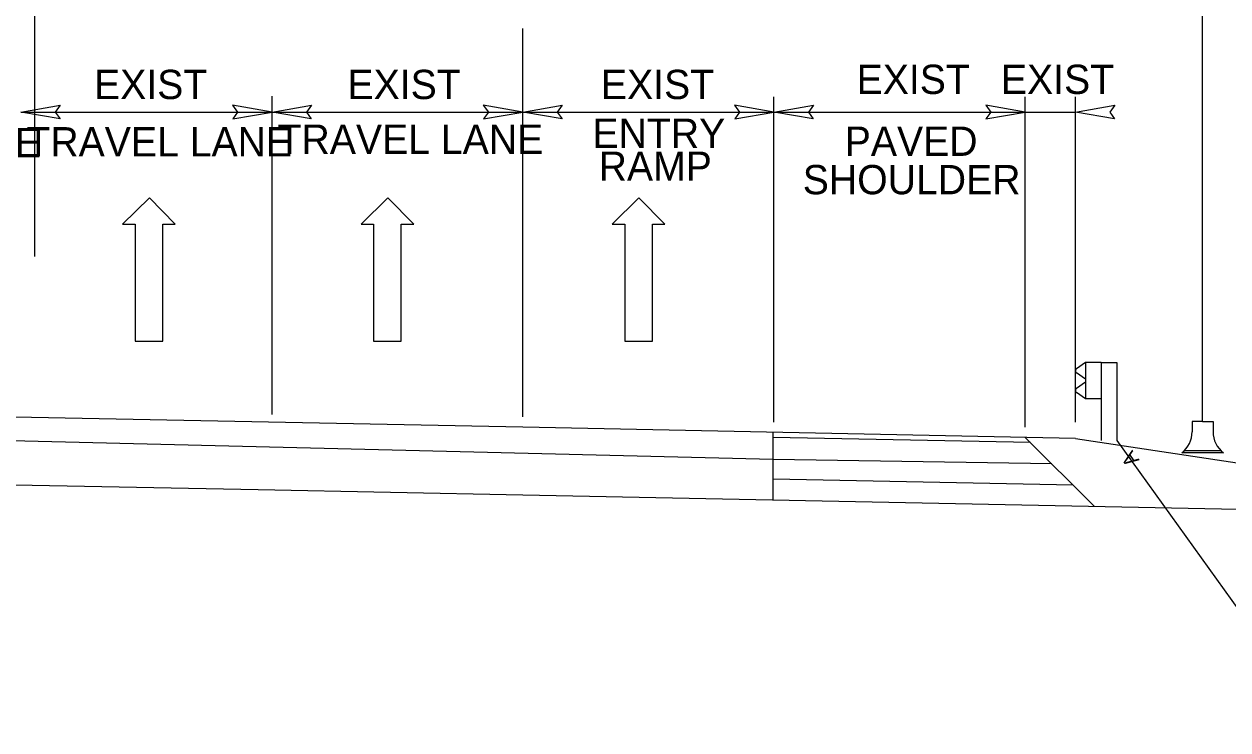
# Model space of a CAD drawing. Extents: x 1726790 to 1728895, y 539219 to 541550.
# Drawn here: x 1727460.3 to 1727517.9, y 539494.9 to 539528.7 of the extents above; entities that cross this region are included whole.
import ezdxf

# ---------------------------------------------------------------- set-up
doc = ezdxf.new("R2010")
doc.units = 0
for name, color, linetype in [('Default', 7, 'Continuous'), ('Scratch_Level_0', 7, 'Continuous'), ('Typical Pavement Slope CELL', 7, 'Continuous'), ('Typical Pavement Slope Information CELL', 7, 'Continuous')]:
    doc.layers.add(name, color=color, linetype=linetype)

msp = doc.modelspace()

# ---------------------------------------------------------------- linework, layer by layer
at = {"layer": 'Default'}
for p, q in [((1727516.682, 539509.702), (1727516.682, 539545.034)), ((1727484.179, 539509.915), (1727484.179, 539528.496)), ((1727472.192, 539510.038), (1727472.192, 539525.257)), ((1727484.179, 539509.915), (1727484.179, 539525.257)), ((1727496.188, 539509.675), (1727496.188, 539525.232)), ((1727508.197, 539509.675), (1727508.197, 539525.232)), ((1727508.197, 539509.435), (1727508.197, 539525.232)), ((1727510.599, 539509.675), (1727510.599, 539525.232)), ((1727460.183, 539524.493), (1727472.192, 539524.493)), ((1727472.192, 539524.493), (1727484.201, 539524.493)), ((1727484.201, 539524.493), (1727496.21, 539524.493)), ((1727496.21, 539524.493), (1727508.219, 539524.493)), ((1727496.21, 539524.493), (1727508.219, 539524.493)), ((1727508.219, 539524.493), (1727510.599, 539524.493)), ((1727466.326, 539520.397), (1727465.046, 539519.137)), ((1727467.566, 539519.137), (1727466.326, 539520.397)), ((1727477.725, 539520.397), (1727476.445, 539519.137)), ((1727478.965, 539519.137), (1727477.725, 539520.397)), ((1727489.734, 539520.397), (1727488.454, 539519.137)), ((1727490.974, 539519.137), (1727489.734, 539520.397)), ((1727465.046, 539519.137), (1727465.646, 539519.137)), ((1727465.646, 539519.137), (1727465.646, 539513.537)), ((1727466.966, 539513.537), (1727466.966, 539519.137)), ((1727466.966, 539519.137), (1727467.566, 539519.137)), ((1727476.445, 539519.137), (1727477.045, 539519.137)), ((1727477.045, 539519.137), (1727477.045, 539513.537)), ((1727478.365, 539513.537), (1727478.365, 539519.137)), ((1727478.365, 539519.137), (1727478.965, 539519.137)), ((1727488.454, 539519.137), (1727489.054, 539519.137)), ((1727489.054, 539519.137), (1727489.054, 539513.537)), ((1727490.374, 539513.537), (1727490.374, 539519.137)), ((1727490.374, 539519.137), (1727490.974, 539519.137)), ((1727465.646, 539513.537), (1727466.966, 539513.537)), ((1727477.045, 539513.537), (1727478.365, 539513.537)), ((1727489.054, 539513.537), (1727490.374, 539513.537)), ((1727516.682, 539509.702), (1727516.182, 539509.702)), ((1727516.182, 539509.702), (1727516.182, 539509.202)), ((1727516.682, 539509.702), (1727517.182, 539509.702)), ((1727517.182, 539509.702), (1727517.182, 539509.202)), ((1727512.577, 539508.786), (1727522.515, 539494.949)), ((1727517.682, 539508.202), (1727515.682, 539508.202)), ((1727517.564, 539508.302), (1727515.799, 539508.302))]:
    msp.add_line(p, q, dxfattribs=at)
for points in [[(1727462.059, 539524.17), (1727460.183, 539524.493), (1727462.069, 539524.826), (1727461.83, 539524.493)], [(1727470.317, 539524.17), (1727472.192, 539524.493), (1727470.306, 539524.826), (1727470.546, 539524.493)], [(1727474.068, 539524.17), (1727472.192, 539524.493), (1727474.078, 539524.826), (1727473.839, 539524.493)], [(1727482.304, 539524.17), (1727484.179, 539524.493), (1727482.293, 539524.826), (1727482.533, 539524.493)], [(1727486.055, 539524.17), (1727484.179, 539524.493), (1727486.065, 539524.826), (1727485.826, 539524.493)], [(1727494.313, 539524.17), (1727496.188, 539524.493), (1727494.302, 539524.826), (1727494.542, 539524.493)], [(1727498.064, 539524.17), (1727496.188, 539524.493), (1727498.074, 539524.826), (1727497.834, 539524.493)], [(1727506.321, 539524.17), (1727508.197, 539524.493), (1727506.311, 539524.826), (1727506.551, 539524.493)], [(1727512.474, 539524.17), (1727510.599, 539524.493), (1727512.485, 539524.826), (1727512.245, 539524.493)]]:
    msp.add_lwpolyline(points, close=True, dxfattribs=at)
for centre, start, end in [((1727514.932, 539509.202), 306.8699, 0), ((1727518.432, 539509.202), 180, 233.1301)]:
    msp.add_arc(centre, 1.25, start, end, dxfattribs=at)
at = {"layer": 'Scratch_Level_0'}
msp.add_line((1727460.834, 539541.109), (1727460.834, 539517.587), dxfattribs=at)
at = {"layer": 'Typical Pavement Slope CELL'}
for p, q in [((1727511.083, 539512.517), (1727510.649, 539512.213)), ((1727511.083, 539511.717), (1727510.649, 539512.022)), ((1727511.83, 539512.517), (1727511.083, 539512.517)), ((1727511.083, 539512.517), (1727511.083, 539510.776)), ((1727511.83, 539512.517), (1727511.83, 539508.786)), ((1727511.83, 539512.517), (1727512.577, 539512.517)), ((1727512.577, 539512.517), (1727512.577, 539508.786)), ((1727511.083, 539511.577), (1727510.649, 539511.272)), ((1727511.083, 539510.776), (1727510.649, 539511.081)), ((1727484.179, 539509.422), (1727437.334, 539510.358)), ((1727511.83, 539510.776), (1727511.083, 539510.776)), ((1727496.148, 539507.879), (1727437.334, 539509.336)), ((1727510.599, 539508.893), (1727484.179, 539509.422)), ((1727496.15, 539505.934), (1727496.15, 539509.182)), ((1727508.449, 539508.69), (1727496.15, 539508.935)), ((1727508.197, 539508.941), (1727511.511, 539505.627)), ((1727510.601, 539508.893), (1727535.395, 539505.143)), ((1727509.469, 539507.669), (1727496.15, 539507.879)), ((1727471.521, 539506.427), (1727437.334, 539507.111)), ((1727510.49, 539506.648), (1727496.15, 539506.935)), ((1727484.179, 539506.174), (1727471.521, 539506.427)), ((1727536.901, 539505.119), (1727484.179, 539506.174))]:
    msp.add_line(p, q, dxfattribs=at)
for centre, start, end in [((1727510.715, 539512.117), 125.00297, 235.0112), ((1727510.715, 539511.176), 125.0059, 235.0366)]:
    msp.add_arc(centre, 0.117, start, end, dxfattribs=at)

# ---------------------------------------------------------------- texts
at = {"layer": 'Default'}
msp.add_text('A', height=0.7, rotation=125.6878, dxfattribs=at).set_placement((1727513.677, 539507.853))
at = {"layer": 'Typical Pavement Slope Information CELL'}
for s, height, p in [('EXIST', 1.401, (1727463.68, 539525.119)), ('EXIST', 1.401, (1727475.798, 539525.119)), ('EXIST', 1.401, (1727487.915, 539525.119)), ('EXIST', 1.401, (1727500.14, 539525.364)), ('EXIST', 1.401, (1727507.038, 539525.364)), ('ENTRY', 1.401, (1727487.511, 539522.786)), ('TRAVEL LANE', 1.40103, (1727448.437, 539522.339)), ('TRAVEL LANE', 1.40103, (1727460.446, 539522.377)), ('TRAVEL LANE', 1.40103, (1727472.455, 539522.5)), ('PAVED', 1.401, (1727499.571, 539522.403)), ('RAMP', 1.401, (1727487.806, 539521.21)), ('SHOULDER', 1.401, (1727497.565, 539520.567))]:
    msp.add_text(s, height=height, dxfattribs=at).set_placement(p)

doc.saveas('drawing.dxf')
